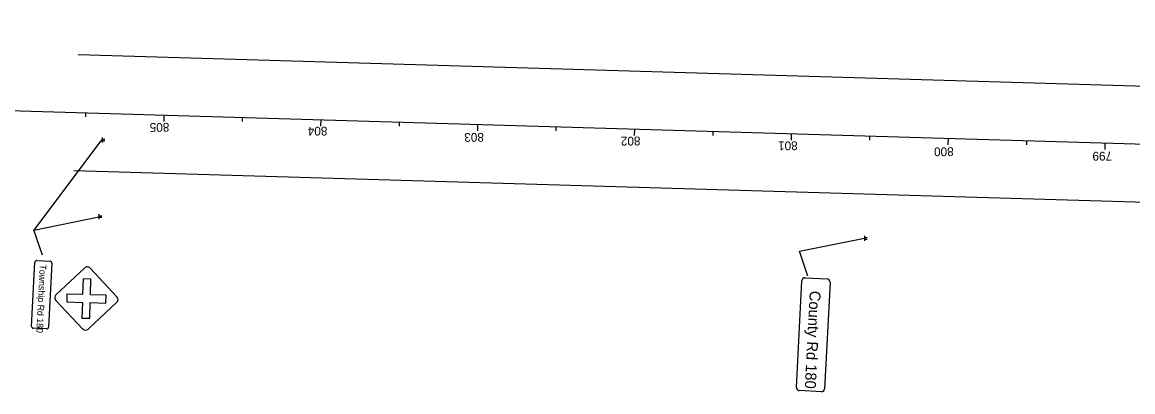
# Model space of a CAD drawing. Extents: x 1658454 to 1663955, y 480219 to 484109.
# Drawn here: x 1660362 to 1661070, y 482563 to 482799 of the extents above; entities that cross this region are included whole.
import ezdxf

# ---------------------------------------------------------------- set-up
doc = ezdxf.new("R2010")
doc.units = 0
for name, color, linetype in [('Default', 7, 'Continuous'), ('PM_P_Lane_Line', 7, 'Continuous'), ('PM_X_Lane_Line', 7, 'Continuous'), ('SC_Scratch1', 7, 'Continuous'), ('SN_X_Public', 7, 'Continuous'), ('SV_X_CL_Survey_50', 7, 'Continuous'), ('SV_X_Text', 7, 'Continuous')]:
    doc.layers.add(name, color=color, linetype=linetype)

msp = doc.modelspace()

# ---------------------------------------------------------------- linework, layer by layer
at = {"layer": 'Default'}
for p, q in [((1660402.81, 482741), (1660402.74, 482738.6)), ((1660452.78, 482739.52), (1660452.67, 482735.52)), ((1660502.76, 482738.03), (1660502.69, 482735.63)), ((1660552.74, 482736.55), (1660552.62, 482732.55)), ((1660602.72, 482735.06), (1660602.65, 482732.66)), ((1660652.7, 482733.58), (1660652.58, 482729.58)), ((1660702.67, 482732.1), (1660702.6, 482729.7)), ((1660752.65, 482730.61), (1660752.53, 482726.61)), ((1660802.63, 482729.13), (1660802.56, 482726.73)), ((1660852.61, 482727.64), (1660852.49, 482723.65)), ((1660902.59, 482726.16), (1660902.52, 482723.76)), ((1660952.56, 482724.68), (1660952.45, 482720.68)), ((1661002.54, 482723.19), (1661002.47, 482720.79)), ((1661052.52, 482721.71), (1661052.4, 482717.71))]:
    msp.add_line(p, q, dxfattribs=at)
at = {"layer": 'PM_P_Lane_Line'}
msp.add_line((1661381.08, 482674.94), (1660395.32, 482704.21), dxfattribs=at)
at = {"layer": 'PM_X_Lane_Line'}
msp.add_line((1661100.95, 482757.29), (1660398.07, 482778.16), dxfattribs=at)
at = {"layer": 'SC_Scratch1'}
for p, q in [((1660413.04, 482723.97), (1660369.9, 482666.31)), ((1660368.45, 482605.02), (1660370.55, 482645.86)), ((1660371.76, 482646.96), (1660380.24, 482646.52)), ((1660381.33, 482645.31), (1660379.24, 482604.47)), ((1660401.25, 482635.28), (1660400.95, 482625.29)), ((1660406.24, 482635.14), (1660401.25, 482635.28)), ((1660405.95, 482625.14), (1660406.24, 482635.14)), ((1660855.92, 482566.06), (1660859.41, 482634.13)), ((1660861.42, 482635.95), (1660875.56, 482635.23)), ((1660877.38, 482633.21), (1660873.89, 482565.14)), ((1660390.95, 482625.59), (1660390.81, 482620.59)), ((1660400.95, 482625.29), (1660390.95, 482625.59)), ((1660415.94, 482624.84), (1660405.95, 482625.14)), ((1660415.79, 482619.85), (1660415.94, 482624.84)), ((1660390.81, 482620.59), (1660400.8, 482620.29)), ((1660400.8, 482620.29), (1660400.5, 482610.3)), ((1660405.5, 482610.15), (1660405.8, 482620.14)), ((1660405.8, 482620.14), (1660415.79, 482619.85)), ((1660400.5, 482610.3), (1660405.5, 482610.15)), ((1660378.03, 482603.37), (1660369.55, 482603.81)), ((1660871.88, 482563.32), (1660857.74, 482564.04))]:
    msp.add_line(p, q, dxfattribs=at)
for points in [[(1660375.32, 482650.47), (1660369.9, 482666.31), (1660411.39, 482674.75)], [(1660863.3, 482637.03), (1660857.87, 482652.87), (1660899.36, 482661.31)], [(1660402.18, 482642.21), (1660383.99, 482625.06)], [(1660422.86, 482623.91), (1660405.72, 482642.1)], [(1660383.88, 482621.53), (1660401.03, 482603.33)], [(1660404.56, 482603.23), (1660422.76, 482620.37)]]:
    msp.add_lwpolyline(points, dxfattribs=at)
for centre, radius, start, end in [((1660371.7, 482645.81), 1.15, 87.06499, 177.06499), ((1660380.18, 482645.37), 1.15, 357.06499, 87.06499), ((1660403.9, 482640.39), 2.5, 43.29934, 133.29934), ((1660861.32, 482634.04), 1.92, 87.06499, 177.06499), ((1660875.47, 482633.31), 1.92, 357.06499, 87.06499), ((1660385.7, 482623.24), 2.5, 133.29934, 223.29934), ((1660421.04, 482622.19), 2.5, 313.29934, 43.29934), ((1660369.61, 482604.96), 1.15, 177.06499, 267.06499), ((1660378.09, 482604.53), 1.15, 267.06499, 357.06499), ((1660402.85, 482605.05), 2.5, 223.29934, 313.29934), ((1660857.83, 482565.96), 1.92, 177.06499, 267.06499), ((1660871.98, 482565.24), 1.92, 267.06499, 357.06499)]:
    msp.add_arc(centre, radius, start, end, dxfattribs=at)
at = {"layer": 'SN_X_Public'}
for p, q in [((1660413.57, 482722.21), (1660413.55, 482725.41)), ((1660413.55, 482724.29), (1660415.15, 482724.3)), ((1660413.56, 482723.81), (1660413.56, 482723.81)), ((1660413.56, 482723.33), (1660415.16, 482723.34)), ((1660411.62, 482673.4), (1660411.6, 482676.6)), ((1660411.61, 482675.48), (1660413.21, 482675.49)), ((1660411.61, 482675), (1660411.61, 482675)), ((1660411.62, 482674.52), (1660413.22, 482674.53)), ((1660899.49, 482659.55), (1660899.47, 482662.75)), ((1660899.48, 482661.63), (1660901.08, 482661.64)), ((1660899.48, 482661.15), (1660899.48, 482661.15)), ((1660899.49, 482660.67), (1660901.09, 482660.68))]:
    msp.add_line(p, q, dxfattribs=at)
at = {"layer": 'SV_X_CL_Survey_50'}
msp.add_line((1663951.73, 482635.63), (1658453.66, 482798.87), dxfattribs=at)

# ---------------------------------------------------------------- texts
at = {"layer": 'SC_Scratch1'}
for s, height, p in [('Township Rd 180', 4.2005, (1660373.69, 482644.56)), ('County Rd 180', 7.0009, (1660864.44, 482627.81))]:
    msp.add_text(s, height=height, rotation=267.06499, dxfattribs=at).set_placement(p)
at = {"layer": 'SV_X_Text'}
for s, p in [('805', (1660456.19, 482734.7)), ('804', (1660556.95, 482732.29)), ('803', (1660656.7, 482728.33)), ('802', (1660756.49, 482725.95)), ('801', (1660856.69, 482722.95)), ('800', (1660956.11, 482719.18)), ('799', (1661057.08, 482716.34))]:
    msp.add_text(s, height=5.6, rotation=180.53411, dxfattribs=at).set_placement(p)

doc.saveas('drawing.dxf')
